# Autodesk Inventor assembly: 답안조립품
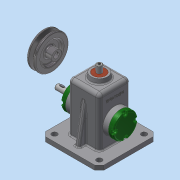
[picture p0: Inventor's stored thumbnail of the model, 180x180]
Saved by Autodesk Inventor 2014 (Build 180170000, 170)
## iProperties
Created: 2016-02
Part Number: 답안조립품
Document SubType Name: Assembly
Designer: 406-강의용
Author: 406-강의용
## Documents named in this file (12)
- C:\Users\406-강의용\Desktop\460211V1020\답안조립품.iam
- C:\Users\406-강의용\Desktop\460211V1020\본체.ipt
- C:\Users\406-강의용\Desktop\460211V1020\뒤커버.ipt
- C:\Users\406-강의용\Desktop\460211V1020\앞커버.ipt
- C:\Users\406-강의용\Desktop\460211V1020\베어링 12 x 32 x 10.ipt
- C:\Users\406-강의용\Desktop\460211V1020\편심축.ipt
- C:\Users\406-강의용\Desktop\460211V1020\링크.ipt
- C:\Users\406-강의용\Desktop\460211V1020\핀 5 x 18.ipt
- C:\Users\406-강의용\Desktop\460211V1020\슬라이드.ipt
- C:\Users\406-강의용\Desktop\460211V1020\부시.ipt
- C:\Users\406-강의용\Desktop\460211V1020\키 4 x 4 x 10.ipt
- C:\Users\406-강의용\Desktop\460211V1020\V벨트풀리.ipt
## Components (2 placed, 2 different names)
1. 핀 5 x 18:1
2. V벨트풀리:1
